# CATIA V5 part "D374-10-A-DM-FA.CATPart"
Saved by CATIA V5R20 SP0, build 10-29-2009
Part number: D374-10-A-DM-FA
Bounding box of the stored display mesh (mm): x -12 to 0.35, y -5 to 5, z -5 to 5
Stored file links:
  C:\Users\Utente\Desktop\IO LAVORO\3D X SITO CF\X SITO\PLASTICA\D374\D374-10-A-DM-FA.CATPart
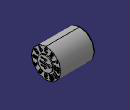
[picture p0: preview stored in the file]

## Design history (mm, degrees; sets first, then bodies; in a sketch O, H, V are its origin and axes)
Set1
  DatumSurface1 to DatumSurface222 "D374-10-A-DM-FA"
Body1 (main body)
